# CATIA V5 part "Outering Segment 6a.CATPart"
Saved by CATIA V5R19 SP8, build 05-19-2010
Part number: Outering Segment 6a
Bounding box of the stored display mesh (mm): x -20 to 20, y 432.68 to 613.614, z 686.3 to 770
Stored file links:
  G:\EU_thinkMotion\CFAO_2010\MMS_groupe3\MMS_groupe3\A reprendre\fovide\fovide\Outering Segment 6a.CATPart
  G:\EU_thinkMotion\CFAO_2010\MMS_groupe3\MMS_groupe3\A reprendre\fovide\fovide\fovide.CATProduct
  G:\EU_thinkMotion\CFAO_2010\MMS_groupe3\MMS_groupe3\A reprendre\fovide\fovide\Linear Actuator Sup B.CATPart
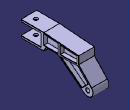
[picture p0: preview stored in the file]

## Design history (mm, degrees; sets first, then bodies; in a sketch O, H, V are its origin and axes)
Set1
  Plane1: linked copy from another document
  DatumCurve1: linked copy from another document
  Plane2: linked copy from another document
  Point1 "Point.C": linked copy from another document
  Line1: linked copy from another document
  Line2: linked copy from another document
Body1 (main body)
  Sketch1 on Plane1, origin (0, 0, 0), H (0, 1, 0), V (0, 0, 1)
    line L1 (432.6795, 770) -> (490.0554, 770)
    line L2 (482.6795, 765) -> (432.6795, 765)
    line L3 (432.6795, 765) -> (432.6795, 770)
    reference projected line E1 (432.6795, 745) -> (432.6795, 755) from edge of DatumCurve1
    line L4 (432.6795, 735) -> (482.6795, 735)
    line L5 (490.1365, 730) -> (432.6795, 730)
    line L6 (432.6795, 730) -> (432.6795, 735)
    reference projected line E2 (432.6795, 745) -> (432.6795, 755) from DatumCurve1
    reference intersected line E3 through (0, 750) direction (-1, 0) from Plane2
    reference intersected line E4 through (0, 750) direction (-1, 0) from Plane2
    arc A1 centre (600, 700) radius 13.7003 from (609.7006, 709.6745) to (591.5146, 689.2437) cw
    point P9 (600, 700)
    reference projected point E5 (600, 700) from Point1
    line L7 (609.7006, 709.6745) -> (577.3223, 743.9159)
    line L8 (591.5146, 689.2437) -> (545.0416, 725.2269)
    line L9 (490.0554, 770) -> (577.3223, 763.1627)
    line L10 (577.3223, 763.1627) -> (577.3223, 743.9159)
    line L11 (490.1365, 730) -> (495.5074, 740.2897)
    line L12 (495.5074, 740.2897) -> (525.5878, 740.2897)
    point P16 (525.5878, 740.2897)
    line L13 (525.5878, 740.2897) -> (545.0416, 725.2269)
    point P17 (525.5878, 740.2897)
    line L14 (482.6795, 765) -> (482.6795, 735)
    distance L2 E3 = 15
    distance L4 E4 = 15
    distance L2 L1 = 5
    distance L4 L5 = 5
    length L2 = 50
    length L4 = 50
    horizontal: L1 H, L2 H, L4 H, L5 H, L12 H
    vertical: L3 V, L6 V, L10 V
    coincidence: L3 E1, L6 E2, P9 E5, P16 L8, P17 L12, P17 L8, P16 P17
    parallelism: L13 L8
  Pad1: profile Sketch1, direction (1, 0, 0), length 20, mirrored extent
  Sketch2 on face of Pad1 from Sketch1.L1, origin (0, 450, 770), H (1, 0, 0), V (0, 1, 0)
    point P1 (0, 0)
    intersected point E1 (0, 0) from Line1
    coincidence: E1 P1
  Hole1: placed by Sketch2, at (0, 450, 770) direction (0, 0, -1), diameter 10, through (limit type 3)
  Sketch3 on end face of Pad1, origin (20, 0, 0), H (0, 1, 0), V (0, 0, 1)
    line L1 (489.8689, 766.8215) -> (489.8689, 742.5544)
    line L2 (489.8689, 742.5544) -> (525.5784, 742.5544)
    line L3 (489.8689, 766.8215) -> (525.5784, 764.0237)
    reference projected line E1 (577.3223, 763.1627) -> (490.0554, 770) from edge [face of Pad1 from Sketch1.L9 | end face of Pad1]
    line L4 (525.5784, 764.0237) -> (525.5784, 742.5544)
    vertical: L1 V, L4 V
    horizontal: L2 H
    parallelism: L3 E1
  Pocket1: profile Sketch3, direction (-1, 0, 0), length 10
  Sketch4 on end face of Pad1, origin (20, 0, 0), H (0, 1, 0), V (0, 0, 1)
    line L1 (530.8158, 763.3863) -> (572.6005, 760.1125)
    reference projected line E1 (577.3223, 763.1627) -> (490.0554, 770) from edge [face of Pad1 from Sketch1.L9 | end face of Pad1]
    line L2 (572.6005, 760.1125) -> (572.6005, 744.0607)
    line L3 (530.8158, 763.3863) -> (530.8158, 742.7244)
    line L4 (530.8158, 742.7244) -> (572.6005, 744.0607)
    parallelism: L1 E1
    vertical: L2 V, L3 V
  Pocket2: profile Sketch4, direction (-1, 0, 0), length 10
  Sketch5 on end face of Pad1, origin (20, 0, 0), H (0, 1, 0), V (0, 0, 1)
    line L1 (533.5627, 738.6427) -> (575.6421, 739.9884)
    reference projected line E1 (530.8158, 742.7244) -> (572.6005, 744.0607) from edge [end face of Pad1 | face of Pocket2 from Sketch4.L4]
    line L2 (575.6421, 739.9884) -> (600.9221, 713.2538)
    reference projected line E2 (609.7006, 709.6745) -> (577.3223, 743.9159) from edge [face of Pad1 from Sketch1.L7 | end face of Pad1]
    line L3 (533.5627, 738.6427) -> (585.3124, 698.5739)
    point P4 (585.3124, 698.5739)
    reference projected line E3 (545.0416, 725.2269) -> (591.5146, 689.2437) from edge [face of Pad1 from Sketch1.L8 | end face of Pad1]
    line L4 (585.3124, 698.5739) -> (600.9221, 713.2538)
    point P5 (585.3124, 698.5739)
    parallelism: L1 E1, L2 E2, L3 E3
    coincidence: P5 L3, P4 P5
  Pocket3: profile Sketch5, direction (-1, 0, 0), length 10
  Sketch6 on start face of Pad1, origin (-20, 0, 0), H (0, -1, 0), V (0, 0, 1)
    line L1 (-489.838, 742.807) -> (-489.838, 767.1315)
    line L2 (-489.838, 742.807) -> (-525.5942, 742.807)
    line L3 (-489.838, 767.1315) -> (-525.5942, 764.3301)
    reference projected line E1 (-577.3223, 763.1627) -> (-490.0554, 770) from edge [start face of Pad1 | face of Pad1 from Sketch1.L9]
    line L4 (-525.5942, 764.3301) -> (-525.5942, 742.807)
    vertical: L1 V, L4 V
    horizontal: L2 H
    parallelism: L3 E1
  Pocket4: profile Sketch6, direction (1, 0, 0), length 10
  Sketch7 on start face of Pad1, origin (-20, 0, 0), H (0, -1, 0), V (0, 0, 1)
    line L1 (-530.3166, 763.862) -> (-574.1191, 760.4302)
    reference projected line E1 (-577.3223, 763.1627) -> (-490.0554, 770) from edge [start face of Pad1 | face of Pad1 from Sketch1.L9]
    line L2 (-530.3166, 763.862) -> (-530.3166, 743.0123)
    line L3 (-574.1191, 760.4302) -> (-574.1191, 744.1819)
    line L4 (-530.3166, 743.0123) -> (-574.1191, 744.1819)
    parallelism: L1 E1
    vertical: L2 V, L3 V
  Pocket5: profile Sketch7, direction (1, 0, 0), length 10
  Sketch8 on start face of Pad1, origin (-20, 0, 0), H (0, -1, 0), V (0, 0, 1)
    line L1 (-575.9084, 741.276) -> (-530.781, 740.071)
    reference projected line E1 (-574.1191, 744.1819) -> (-530.3166, 743.0123) from edge [start face of Pad1 | face of Pocket5 from Sketch7.L4]
    line L2 (-530.781, 740.071) -> (-582.1774, 700.2757)
    reference projected line E2 (-545.0416, 725.2269) -> (-591.5146, 689.2437) from edge [start face of Pad1 | face of Pad1 from Sketch1.L8]
    line L3 (-575.9084, 741.276) -> (-599.1828, 716.6623)
    reference projected line E3 (-609.7006, 709.6745) -> (-577.3223, 743.9159) from edge [start face of Pad1 | face of Pad1 from Sketch1.L7]
    line L4 (-599.1828, 716.6623) -> (-582.1774, 700.2757)
    parallelism: L1 E1, L2 E2, L3 E3
  Pocket6: profile Sketch8, direction (1, 0, 0), length 10
  Sketch9 on end face of Pad1, origin (20, 600, 700), H (0, 1, 0), V (0, 0, 1)
    point P1 (0, 0)
    intersected point E1 (0, 0) from Line2
    coincidence: E1 P1
  Hole2: placed by Sketch9, at (20, 600, 700) direction (-1, 0, 0), diameter 10, through (limit type 6)
  Fillet1: radius 0.5, on end face of Pad1; start face of Pad1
